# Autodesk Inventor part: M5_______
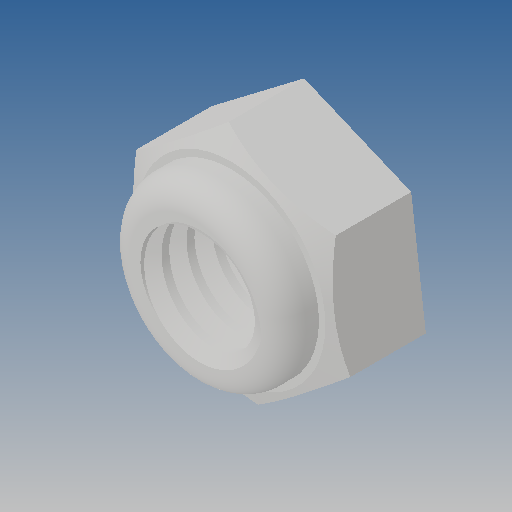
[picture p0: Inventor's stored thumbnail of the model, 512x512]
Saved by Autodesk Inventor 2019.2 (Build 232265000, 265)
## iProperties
Created: 2010-06
Part Number: M5_______
Material: Ogólny
Document SubType Name: Modeling
Designer: CADENGINEERING4
Density: 1 g/cm^3
Appearance: Domyślna
Author: CADENGINEERING4
Revision Number: ANY
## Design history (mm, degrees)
feature "NONE"
node "Bryła1"
